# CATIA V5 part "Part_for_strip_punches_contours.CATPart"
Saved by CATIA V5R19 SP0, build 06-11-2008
Publications: "BoundaryStrip", "2Steps_CuttingLine", "Punch1Boundary", "Punch2Boundary", "Punch3Boundary", "Punch4Boundary", "Punch5Boundary", "Punch6Boundary"
Bounding box of the stored display mesh (mm): x -45.182 to 741.192, y -88.967 to 51.033, z -6.847 to 23.79
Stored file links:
  E:\ISPSL9StripLayoutDesign.d\SL9\Starting_Data\Part_for_strip_punches_contours.CATPart
  E:\Essais\SLD_R17\demo linked\demo-link.CATProduct
  E:\ISPSL9StripLayoutDesign.d\SL9\Starting_Data\Part_for_Strip.CATPart
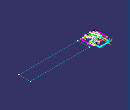
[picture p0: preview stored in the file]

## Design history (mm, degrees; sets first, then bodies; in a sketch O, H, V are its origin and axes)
Parameters
  Step_Length = 55 mm
  Number_Of_Steps = 10
  Strip_Width = 120 mm
  Rotation_Part = 60 deg
  Part_Thickness = 2 mm
  Scrap_Area = 0.00288853 (area) {= area(Sketch4 )-area(Translate1 )}
  `%SCRAP` = 44 {= round(Scrap_Area /area(Sketch4)*100)}
SheetMetalParameters1: BendRadius 4, ReliefAxialLength 2, ReliefRadialLength 1, MinimumBendRadius 0, Thickness 2, KFactor 0.400515 {= log(min(100,max(20*SheetMetalParameters1.BendRadius,SheetMetalParameters1.Thickness)/SheetMetalParameters1.Thickness))/log(100)/2}
Set1
  Line1: linked copy from another document
Set2 "Datas_For_Strip"
  Extract1
  Boundary1
  Near1
  Plane1: type OffsetPt
Set3 "Strip_Definition"
  Set4 "OverAll_Boundary_Datas"
    Extremum1
    Extremum2
    Extremum3
    Translate1
    Extremum4
    Sketch1 "OverAll_Boundary" on xy-plane, origin (0, 0, 0), H (1, 0, 0), V (0, 1, 0)
      line L1 (-45.1822, 38.1665) -> (107.5661, 38.1665)
      line L2 (107.5661, 38.1665) -> (107.5661, -76.1007)
      line L3 (107.5661, -76.1007) -> (-45.1822, -76.1007)
      line L4 (-45.1822, -76.1007) -> (-45.1822, 38.1665)
      reference projected point E1 (107.5661, 22.5665) from Extremum4
      reference projected point E2 (-0.3202, -76.1007) from Extremum2
      reference projected point E3 (41.4461, 38.1665) from Extremum1
      reference projected point E4 (-45.1822, -32.0913) from Extremum3
      horizontal: L1 H, L3 H
      vertical: L2 V, L4 V
      coincidence: L2 E1, L3 E2, L1 E3, L4 E4
    Sketch2 on Plane1, origin (0, 0, 0), H (1, 0, 0), V (0, 1, 0)
      line L1 (27.4232, -14.0108) -> (-4.8037, -14.0108)
      line L2 (-4.8037, -14.0108) -> (42.6816, 17.805)
      line L3 (42.6816, 17.805) -> (48.0592, 9.779)
      line L4 (48.0592, 9.779) -> (27.4232, -14.0108)
      reference projected line E1 (25.9763, -13.7108) -> (-23.4821, -13.7108) from Sketch8.L1
      distance L1 E1 = 0.3
      horizontal: L1 H
      perpendicularity: L3 L2
  Set5 "Strip_Skeleton"
    Sketch3 "Boundary2Steps" on xy-plane, origin (0, 0, 0), H (1, 0, 0), V (0, 1, 0)
      line L1 (-23.808, 41.0329) -> (86.192, 41.0329)
      line L2 (86.192, 41.0329) -> (86.192, -78.9671)
      line L3 (86.192, -78.9671) -> (-23.808, -78.9671)
      line L4 (-23.808, -78.9671) -> (-23.808, 41.0329)
      reference projected line E1 (107.5661, 38.1665) -> (-45.1822, 38.1665) from Sketch1.L1
      reference projected line E2 (-45.1822, -76.1007) -> (107.5661, -76.1007) from Sketch1.L3
      reference projected line E3 (-45.1822, 38.1665) -> (-45.1822, -76.1007) from Sketch1.L4
      reference projected line E4 (107.5661, -76.1007) -> (107.5661, 38.1665) from Sketch1.L2
      construction line L5 (-70.2888, -18.9671) -> (96.3725, -18.9671)
      reference projected line E5 (107.5661, 38.1665) -> (-45.1822, 38.1665) from Sketch1.L1
      reference projected line E6 (-45.1822, -76.1007) -> (107.5661, -76.1007) from Sketch1.L3
      axis line L6 (31.192, -92.2122) -> (31.192, 51.3206)
      reference projected line E7 (107.5661, -76.1007) -> (107.5661, 38.1665) from Sketch1.L2
      reference projected line E8 (-45.1822, 38.1665) -> (-45.1822, -76.1007) from Sketch1.L4
      length L2 = 120 {= Strip_Width}
      length L1 = 110 {= 2*Step_Length}
      distance E1 E2 = 114.2673 (reference)
      distance E3 E4 = 152.7482 (reference)
      horizontal: L1 H, L3 H, L5 H
      vertical: L2 V, L4 V, L6 V
      symmetry: E5 E6 L5, L3 L1 L5, E7 E8 L6, L4 L2 L6
    Sketch4 "Boundary1Step" on xy-plane, origin (0, 0, 0), H (1, 0, 0), V (0, 1, 0)
      point P1 (-23.808, 41.0329)
      line L1 (-23.808, 41.0329) -> (31.192, 41.0329)
      line L2 (31.192, 41.0329) -> (31.192, -78.9671)
      line L3 (31.192, -78.9671) -> (-23.808, -78.9671)
      line L4 (-23.808, -78.9671) -> (-23.808, 41.0329)
      reference projected point E1 (-23.808, 41.0329) from vertex [element of Sketch3 | element of Sketch3]
      length L1 = 55 {= Step_Length}
      length L2 = 120 {= Strip_Width}
      horizontal: L1 H, L3 H
      vertical: L2 V, L4 V
      coincidence: P1 E1
    Sketch5 "BoundaryStrip" on xy-plane, origin (0, 0, 0), H (1, 0, 0), V (0, 1, 0)
      line L1 (136.192, 41.0329) -> (741.192, 41.0329)
      line L2 (741.192, 41.0329) -> (741.192, -78.9671)
      line L3 (741.192, -78.9671) -> (136.192, -78.9671)
      line L4 (136.192, -78.9671) -> (136.192, 41.0329)
      reference projected line E1 (86.192, 41.0329) -> (-23.808, 41.0329) from Sketch3.L1
      reference projected line E2 (86.192, -78.9671) -> (86.192, 41.0329) from Sketch3.L2
      length L1 = 605 {= Step_Length * (Number_Of_Steps + 1)}
      length L2 = 120 {= Strip_Width}
      distance E2 L4 = 50
      horizontal: L1 H, L3 H
      vertical: L2 V, L4 V
      coincidence: L1 E1
    Extract2
  Set6 "Punches_Construction"
    Set7 "Sketch_Punches"
      Sketch6 on Plane1, origin (0, 0, 0), H (1, 0, 0), V (0, 1, 0)
        circle A1 centre (0, -65.2237) radius 5.1261
        point P1 (0, -65.2237)
        coincidence: P1 V
      Sketch7 on Plane1, origin (0, 0, 0), H (1, 0, 0), V (0, 1, 0)
        circle A1 centre (18.8479, 16.6393) radius 4.2895
      Sketch8 on Plane1, origin (0, 0, 0), H (1, 0, 0), V (0, 1, 0)
        line L1 (25.9763, -13.7108) -> (-23.4821, -13.7108)
        line L2 (-23.4821, -13.7108) -> (-23.4821, -31.2218)
        line L3 (-23.4821, -31.2218) -> (25.9763, -31.2218)
        line L4 (25.9763, -31.2218) -> (25.9763, -13.7108)
        horizontal: L1 H, L3 H
        vertical: L2 V, L4 V
      Sketch9 on Plane1, origin (0, 0, 0), H (1, 0, 0), V (0, 1, 0)
        line L1 (29.7251, -30.9218) -> (-26.9679, -30.9218)
        line L2 (-26.9679, -30.9218) -> (-0.5287, -64.1475)
        line L3 (-0.5287, -64.1475) -> (-0.5287, -83.9671)
        line L4 (4.4713, -88.9671) -> (50.6382, -88.9671)
        line L5 (55.6382, -83.9671) -> (55.6382, -67.007)
        line L6 (55.6382, -67.007) -> (29.7251, -30.9218)
        reference projected line E1 (-23.4821, -31.2218) -> (25.9763, -31.2218) from Sketch8.L3
        arc A1 centre (50.6382, -83.9671) radius 5 from (55.6382, -83.9671) to (50.6382, -88.9671) cw
        arc A2 centre (4.4713, -83.9671) radius 5 from (-0.5287, -83.9671) to (4.4713, -88.9671) ccw
        distance L1 E1 = 0.3
        radius A1 = 5
        radius A2 = 5
        horizontal: L1 H, L4 H
        vertical: L3 V, L5 V
        tangency: A1 L5, A1 L4, A2 L3, A2 L4
      Sketch10 on Plane1, origin (0, 0, 0), H (1, 0, 0), V (0, 1, 0)
        line L1 (27.4232, -14.0108) -> (-4.8037, -14.0108)
        line L2 (-4.8037, -14.0108) -> (42.6816, 17.805)
        line L3 (42.6816, 17.805) -> (48.0592, 9.779)
        line L4 (48.0592, 9.779) -> (27.4232, -14.0108)
        reference projected line E1 (25.9763, -13.7108) -> (-23.4821, -13.7108) from Sketch8.L1
        distance L1 E1 = 0.3
        horizontal: L1 H
        perpendicularity: L3 L2
      Sketch11 on Plane1, origin (0, 0, 0), H (1, 0, 0), V (0, 1, 0)
        line L1 (49.751, 6.7151) -> (43.5882, 15.913)
        line L2 (43.5882, 15.913) -> (41.1957, 34.0406)
        line L3 (41.1957, 34.0406) -> (41.1957, 46.0329)
        line L4 (46.1957, 51.0329) -> (92.5694, 51.0329)
        line L5 (97.5694, 46.0329) -> (97.5694, 27.7649)
        line L6 (97.5694, 27.7649) -> (49.751, 6.7151)
        reference projected line E1 (48.0592, 9.779) -> (42.6816, 17.805) from Sketch10.L3
        arc A1 centre (92.5694, 46.0329) radius 5 from (97.5694, 46.0329) to (92.5694, 51.0329) ccw
        arc A2 centre (46.1957, 46.0329) radius 5 from (46.1957, 51.0329) to (41.1957, 46.0329) ccw
        distance L1 E1 = 0.3
        radius A1 = 5
        radius A2 = 5
        vertical: L3 V, L5 V
        horizontal: L4 H
        tangency: A1 L5, A1 L4, A2 L4, A2 L3
    Set8 "Cutting_Shapes"
      Fill1
      Fill2
      Extrude1
      Extrude2
      Join1
    Set9 "* Punch1"
      Split1
      Boundary2
      Fill3
    Set10 "* Punch2"
      Split2
      Boundary3
      Fill4
    Set11 "* Punch3"
      Split3
      Boundary4
      Fill5
    Set12 "* Punch4"
      Split4
      Boundary5
      Fill6
    Set13 "* Punch5"
      Split5
      Boundary6
      Fill7
    Set14 "* Punch6"
      Split6
      Boundary7
      Fill8
  Point1: type OnCurve
  Sketch12 "2Steps_CuttingLine" on Plane1, origin (0, 0, 0), H (1, 0, 0), V (0, 1, 0)
    line L1 (-1.8905, -29.4122) -> (28.8393, -78.9671)
    point P2 (28.8393, -78.9671)
    reference projected line E1 (-23.808, -78.9671) -> (31.192, -78.9671) from Sketch4.L3
    line L2 (-1.8905, -29.4122) -> (29.1773, -0.8566)
    line L3 (29.1773, -0.8566) -> (32.241, 4.45)
    reference projected point E2 (31.192, 2.6329) from Point1
    reference projected line E3 (31.192, 41.0329) -> (-23.808, 41.0329) from Sketch4.L1
    line L4 (32.241, 4.45) -> (60.9506, 21.5697)
    line L5 (60.9506, 21.5697) -> (65.833, 41.0329)
    point P6 (65.833, 41.0329)
    reference projected line E4 (86.192, 41.0329) -> (-23.808, 41.0329) from Sketch3.L1
    angle L3 E3 = 60 {= Rotation_Part}
    coincidence: P2 E1, L3 E2, P6 E4
Body1 (main body)
  Solid1: linked copy from another document
Body2 "NewBody"
  Rotate1
  CloseSurface1
  Recognize1
Body3 "Temporary_Body"
Relations
  Rotate1.Angle = Rotation_Part
  Translate1.Length = Step_Length
  Extrude1.Lim1 = 1.5*Part_Thickness
  Extrude1.Lim2 = 1.5*Part_Thickness
  Extrude2.Lim1 = 1.5*Part_Thickness
  Extrude2.Lim2 = 1.5*Part_Thickness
